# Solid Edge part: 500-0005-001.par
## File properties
Title: Nut
Author: James M. Robinson
Template: NORMAL.PAR
Last saved by: jccrumbl
Revision: 53
Application: Solid Edge
Revision: A
Teamcenter Item Type: Item
Accuracy: 0.99
TC Engineer Description: Valve Nut
TC_ImportTime: 2008-07-08
PartType: -
Last Saved Version: -
File Size: 0
Number of Sheets: 0
Number of Objects: 0
Material: aluminum
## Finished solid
Body 1: solid body, 21 faces, 56 edges, 36 vertices.
  Faces by surface: cone 12, plane 8, cylinder 1
  Edges by curve: intersection 24, line 18, circle 14
Bounding box of the edges (mm): 27.713 x 24.000 x 7.500, from (-13.8564, -12, 0) to (13.8564, 12, 7.5).
Cylindrical faces by radius (mm): R7.5 x1
Conical faces (half-angle, radius in mm at the cone's reference point): 45 deg R10.8787 x6, 45 deg R15.1213 x6
Planar faces by outward normal: +y 1, +z 1, -y 1, -z 1, oblique 4
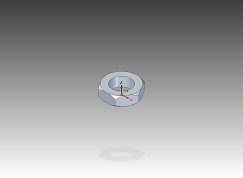
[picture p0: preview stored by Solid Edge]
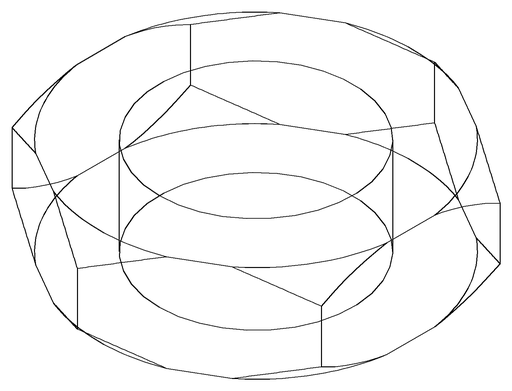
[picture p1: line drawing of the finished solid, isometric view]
